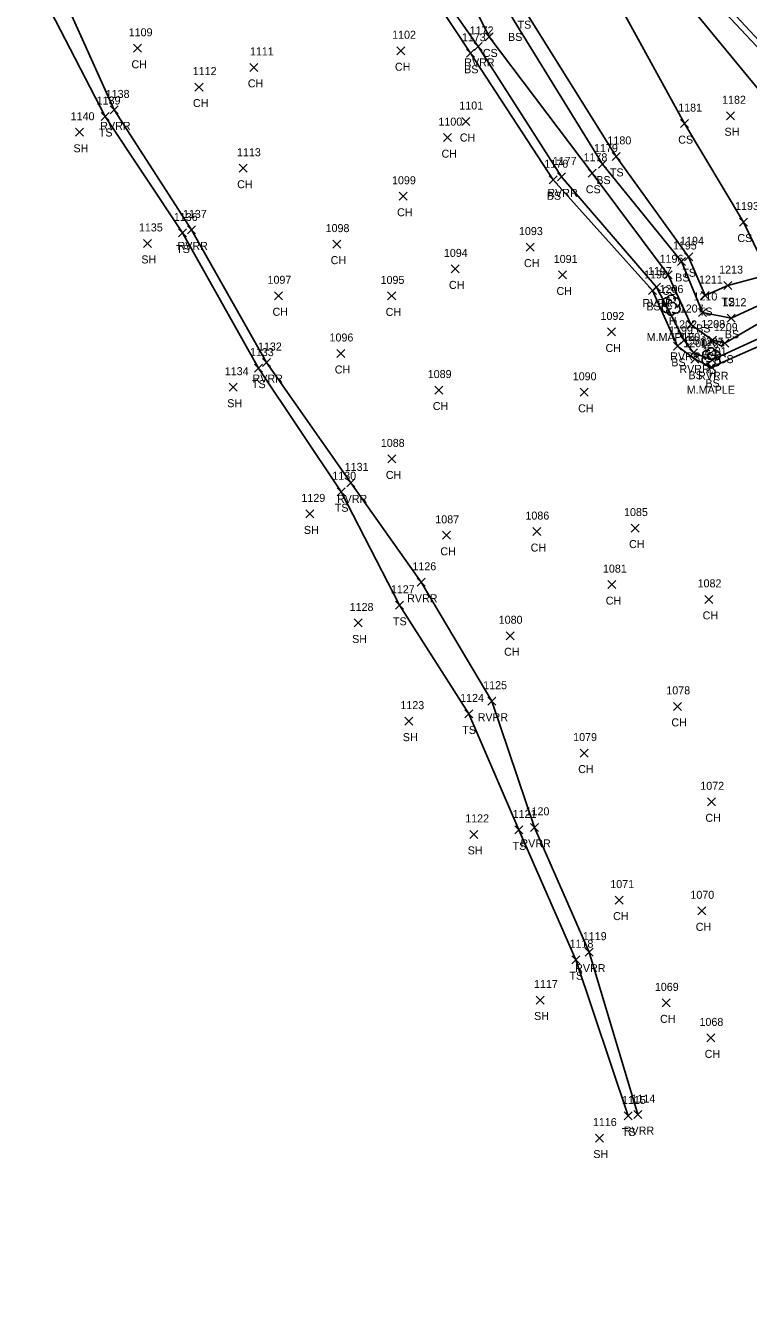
# Model space of a CAD drawing. Extents: x 1469310 to 1475157, y 493997 to 498873.
# Drawn here: x 1469317.8 to 1469498.4, y 498333.7 to 498651.4 of the extents above; entities that cross this region are included whole.
import ezdxf

# ---------------------------------------------------------------- set-up
doc = ezdxf.new("R2010")
doc.units = 0
for name, color, linetype in [('L_A', 7, 'Continuous'), ('L_C', 7, 'Continuous'), ('L_I', 7, 'Continuous'), ('L_TIC', 7, 'Continuous'), ('LAWE', 7, 'Continuous'), ('LELB', 7, 'Continuous'), ('LTD', 7, 'Continuous'), ('PEU', 7, 'Continuous')]:
    doc.layers.add(name, color=color, linetype=linetype)

msp = doc.modelspace()

# ---------------------------------------------------------------- linework, layer by layer
at = {"layer": 'L_TIC'}
for points in [[(1469432.57, 498647.51), (1469434.57, 498649.51)], [(1469434.57, 498647.51), (1469432.57, 498649.51)], [(1469344.77, 498644.67), (1469346.77, 498646.67)], [(1469346.77, 498644.67), (1469344.77, 498646.67)], [(1469410.56, 498644.06), (1469412.56, 498646.06)], [(1469412.56, 498644.06), (1469410.56, 498646.06)], [(1469427.9, 498643.42), (1469429.9, 498645.42)], [(1469429.9, 498643.42), (1469427.9, 498645.42)], [(1469429.85, 498645.13), (1469431.85, 498647.13)], [(1469431.85, 498645.13), (1469429.85, 498647.13)], [(1469373.84, 498639.9), (1469375.84, 498641.9)], [(1469375.84, 498639.9), (1469373.84, 498641.9)], [(1469360.12, 498634.98), (1469362.12, 498636.98)], [(1469362.12, 498634.98), (1469360.12, 498636.98)], [(1469336.69, 498627.62), (1469338.69, 498629.62)], [(1469338.69, 498627.62), (1469336.69, 498629.62)], [(1469338.95, 498629.27), (1469340.95, 498631.27)], [(1469340.95, 498629.27), (1469338.95, 498631.27)], [(1469426.78, 498626.37), (1469428.78, 498628.37)], [(1469428.78, 498626.37), (1469426.78, 498628.37)], [(1469492.89, 498627.81), (1469494.89, 498629.81)], [(1469494.89, 498627.81), (1469492.89, 498629.81)], [(1469330.28, 498623.68), (1469332.28, 498625.68)], [(1469332.28, 498623.68), (1469330.28, 498625.68)], [(1469481.37, 498625.84), (1469483.37, 498627.84)], [(1469483.37, 498625.84), (1469481.37, 498627.84)], [(1469422.21, 498622.34), (1469424.21, 498624.34)], [(1469424.21, 498622.34), (1469422.21, 498624.34)], [(1469464.35, 498617.65), (1469466.35, 498619.65)], [(1469466.35, 498617.65), (1469464.35, 498619.65)], [(1469371.16, 498614.69), (1469373.16, 498616.69)], [(1469373.16, 498614.69), (1469371.16, 498616.69)], [(1469460.92, 498615.73), (1469462.92, 498617.73)], [(1469462.92, 498615.73), (1469460.92, 498617.73)], [(1469448.54, 498611.82), (1469450.54, 498613.82)], [(1469450.54, 498611.82), (1469448.54, 498613.82)], [(1469450.62, 498612.53), (1469452.62, 498614.53)], [(1469452.62, 498612.53), (1469450.62, 498614.53)], [(1469458.29, 498613.44), (1469460.29, 498615.44)], [(1469460.29, 498613.44), (1469458.29, 498615.44)], [(1469411.11, 498607.69), (1469413.11, 498609.69)], [(1469413.11, 498607.69), (1469411.11, 498609.69)], [(1469496.15, 498601.25), (1469498.15, 498603.25)], [(1469498.15, 498601.25), (1469496.15, 498603.25)], [(1469356.01, 498598.52), (1469358.01, 498600.52)], [(1469358.01, 498598.52), (1469356.01, 498600.52)], [(1469358.23, 498599.28), (1469360.23, 498601.28)], [(1469360.23, 498599.28), (1469358.23, 498601.28)], [(1469347.23, 498595.9), (1469349.23, 498597.9)], [(1469349.23, 498595.9), (1469347.23, 498597.9)], [(1469394.52, 498595.73), (1469396.52, 498597.73)], [(1469396.52, 498595.73), (1469394.52, 498597.73)], [(1469442.8, 498594.99), (1469444.8, 498596.99)], [(1469444.8, 498594.99), (1469442.8, 498596.99)], [(1469480.61, 498591.39), (1469482.61, 498593.39)], [(1469482.61, 498591.39), (1469480.61, 498593.39)], [(1469482.42, 498592.57), (1469484.42, 498594.57)], [(1469484.42, 498592.57), (1469482.42, 498594.57)], [(1469424.06, 498589.54), (1469426.06, 498591.54)], [(1469426.06, 498589.54), (1469424.06, 498591.54)], [(1469450.92, 498588.02), (1469452.92, 498590.02)], [(1469452.92, 498588.02), (1469450.92, 498590.02)], [(1469474.38, 498585.01), (1469476.38, 498587.01)], [(1469476.38, 498585.01), (1469474.38, 498587.01)], [(1469477.33, 498588.06), (1469479.33, 498590.06)], [(1469479.33, 498588.06), (1469477.33, 498590.06)], [(1469492.17, 498585.36), (1469494.17, 498587.36)], [(1469494.17, 498585.36), (1469492.17, 498587.36)], [(1469380, 498582.82), (1469382, 498584.82)], [(1469382, 498582.82), (1469380, 498584.82)], [(1469408.24, 498582.79), (1469410.24, 498584.79)], [(1469410.24, 498582.79), (1469408.24, 498584.79)], [(1469473.41, 498584.16), (1469475.41, 498586.16)], [(1469475.41, 498584.16), (1469473.41, 498586.16)], [(1469486.55, 498582.88), (1469488.55, 498584.88)], [(1469488.55, 498582.88), (1469486.55, 498584.88)], [(1469485.84, 498578.65), (1469487.84, 498580.65)], [(1469487.84, 498578.65), (1469485.84, 498580.65)], [(1469482.97, 498575.63), (1469484.97, 498577.63)], [(1469484.97, 498575.63), (1469482.97, 498577.63)], [(1469493.02, 498577.22), (1469495.02, 498579.22)], [(1469495.02, 498577.22), (1469493.02, 498579.22)], [(1469463.17, 498573.78), (1469465.17, 498575.78)], [(1469465.17, 498573.78), (1469463.17, 498575.78)], [(1469479.64, 498570.19), (1469481.64, 498572.19)], [(1469481.64, 498570.19), (1469479.64, 498572.19)], [(1469481.32, 498571.69), (1469483.32, 498573.69)], [(1469483.32, 498571.69), (1469481.32, 498573.69)], [(1469488.34, 498571.76), (1469490.34, 498573.76)], [(1469490.34, 498571.76), (1469488.34, 498573.76)], [(1469491.49, 498570.98), (1469493.49, 498572.98)], [(1469493.49, 498570.98), (1469491.49, 498572.98)], [(1469376.97, 498566.13), (1469378.97, 498568.13)], [(1469378.97, 498566.13), (1469376.97, 498568.13)], [(1469395.54, 498568.4), (1469397.54, 498570.4)], [(1469397.54, 498568.4), (1469395.54, 498570.4)], [(1469483.59, 498568.54), (1469485.59, 498570.54)], [(1469485.59, 498568.54), (1469483.59, 498570.54)], [(1469483.92, 498566.97), (1469485.92, 498568.97)], [(1469485.92, 498566.97), (1469483.92, 498568.97)], [(1469488.26, 498566.84), (1469490.26, 498568.84)], [(1469490.26, 498566.84), (1469488.26, 498568.84)], [(1469374.95, 498564.74), (1469376.95, 498566.74)], [(1469376.95, 498564.74), (1469374.95, 498566.74)], [(1469488.16, 498564.96), (1469490.16, 498566.96)], [(1469490.16, 498564.96), (1469488.16, 498566.96)], [(1469368.69, 498559.97), (1469370.69, 498561.97)], [(1469370.69, 498559.97), (1469368.69, 498561.97)], [(1469420.03, 498559.26), (1469422.03, 498561.26)], [(1469422.03, 498559.26), (1469420.03, 498561.26)], [(1469456.33, 498558.7), (1469458.33, 498560.7)], [(1469458.33, 498558.7), (1469456.33, 498560.7)], [(1469408.3, 498542.05), (1469410.3, 498544.05)], [(1469410.3, 498542.05), (1469408.3, 498544.05)], [(1469398.07, 498536.07), (1469400.07, 498538.07)], [(1469400.07, 498536.07), (1469398.07, 498538.07)], [(1469395.62, 498533.84), (1469397.62, 498535.84)], [(1469397.62, 498533.84), (1469395.62, 498535.84)], [(1469387.83, 498528.31), (1469389.83, 498530.31)], [(1469389.83, 498528.31), (1469387.83, 498530.31)], [(1469469.05, 498524.77), (1469471.05, 498526.77)], [(1469471.05, 498524.77), (1469469.05, 498526.77)], [(1469421.91, 498522.96), (1469423.91, 498524.96)], [(1469423.91, 498522.96), (1469421.91, 498524.96)], [(1469444.47, 498523.89), (1469446.47, 498525.89)], [(1469446.47, 498523.89), (1469444.47, 498525.89)], [(1469415.6, 498511.22), (1469417.6, 498513.22)], [(1469417.6, 498511.22), (1469415.6, 498513.22)], [(1469463.22, 498510.64), (1469465.22, 498512.64)], [(1469465.22, 498510.64), (1469463.22, 498512.64)], [(1469487.42, 498506.95), (1469489.42, 498508.95)], [(1469489.42, 498506.95), (1469487.42, 498508.95)], [(1469410.17, 498505.47), (1469412.17, 498507.47)], [(1469412.17, 498505.47), (1469410.17, 498507.47)], [(1469399.88, 498501.05), (1469401.88, 498503.05)], [(1469401.88, 498501.05), (1469399.88, 498503.05)], [(1469437.84, 498497.86), (1469439.84, 498499.86)], [(1469439.84, 498497.86), (1469437.84, 498499.86)], [(1469433.22, 498481.51), (1469435.22, 498483.51)], [(1469435.22, 498481.51), (1469433.22, 498483.51)], [(1469479.61, 498480.21), (1469481.61, 498482.21)], [(1469481.61, 498480.21), (1469479.61, 498482.21)], [(1469427.48, 498478.32), (1469429.48, 498480.32)], [(1469429.48, 498478.32), (1469427.48, 498480.32)], [(1469412.54, 498476.52), (1469414.54, 498478.52)], [(1469414.54, 498476.52), (1469412.54, 498478.52)], [(1469456.35, 498468.54), (1469458.35, 498470.54)], [(1469458.35, 498468.54), (1469456.35, 498470.54)], [(1469488.1, 498456.36), (1469490.1, 498458.36)], [(1469490.1, 498456.36), (1469488.1, 498458.36)], [(1469440.03, 498449.34), (1469442.03, 498451.34)], [(1469442.03, 498449.34), (1469440.03, 498451.34)], [(1469443.89, 498449.98), (1469445.89, 498451.98)], [(1469445.89, 498449.98), (1469443.89, 498451.98)], [(1469428.73, 498448.22), (1469430.73, 498450.22)], [(1469430.73, 498448.22), (1469428.73, 498450.22)], [(1469465.06, 498431.8), (1469467.06, 498433.8)], [(1469467.06, 498431.8), (1469465.06, 498433.8)], [(1469485.7, 498429.12), (1469487.7, 498431.12)], [(1469487.7, 498429.12), (1469485.7, 498431.12)], [(1469454.23, 498416.9), (1469456.23, 498418.9)], [(1469456.23, 498416.9), (1469454.23, 498418.9)], [(1469457.55, 498418.79), (1469459.55, 498420.79)], [(1469459.55, 498418.79), (1469457.55, 498420.79)], [(1469445.34, 498406.83), (1469447.34, 498408.83)], [(1469447.34, 498406.83), (1469445.34, 498408.83)], [(1469476.8, 498406.12), (1469478.8, 498408.12)], [(1469478.8, 498406.12), (1469476.8, 498408.12)], [(1469487.94, 498397.36), (1469489.94, 498399.36)], [(1469489.94, 498397.36), (1469487.94, 498399.36)], [(1469467.33, 498377.85), (1469469.33, 498379.85)], [(1469469.33, 498377.85), (1469467.33, 498379.85)], [(1469469.69, 498378.21), (1469471.69, 498380.21)], [(1469471.69, 498378.21), (1469469.69, 498380.21)], [(1469460.11, 498372.33), (1469462.11, 498374.33)], [(1469462.11, 498372.33), (1469460.11, 498374.33)]]:
    msp.add_lwpolyline(points, dxfattribs=at)
at = {"layer": 'LAWE'}
for points in [[(1469389.72, 498705.76), (1469405.14, 498682.89), (1469430.85, 498646.13), (1469451.62, 498613.53), (1469475.38, 498586.01), (1469482.32, 498572.69), (1469484.59, 498569.54), (1469489.26, 498567.84), (1469509.66, 498577.17), (1469522.84, 498580.18), (1469533.51, 498579.28), (1469530.31, 498572.64)], [(1469470.69, 498379.21), (1469458.55, 498419.79), (1469444.89, 498450.98), (1469434.22, 498482.51), (1469416.6, 498512.22), (1469399.07, 498537.07), (1469377.97, 498567.13), (1469359.23, 498600.28), (1469339.95, 498630.27), (1469322.53, 498669.03)]]:
    msp.add_lwpolyline(points, dxfattribs=at)
at = {"layer": 'LELB'}
for points in [[(1469416.82, 498734.31), (1469446.33, 498703.1), (1469470.89, 498677.65), (1469509.28, 498636.71), (1469524.42, 498615.8), (1469544.37, 498592.02), (1469564.88, 498563.16), (1469574.6, 498542.86), (1469576.57, 498532.67), (1469562.98, 498525.95), (1469548.2, 498517.37), (1469540.61, 498511.22), (1469554.07, 498484.99), (1469566.51, 498459.59)], [(1469413.42, 498730.94), (1469442.52, 498698.7), (1469468.45, 498674.77), (1469500.53, 498635.82), (1469519, 498614.53), (1469533.17, 498594.86), (1469544.52, 498587.12), (1469562.89, 498554.7), (1469567.79, 498543.52), (1469559.26, 498528.6), (1469545.4, 498521.66), (1469536.79, 498513.03)], [(1469407.36, 498725.91), (1469434.35, 498693.87), (1469460.14, 498667.42), (1469482.37, 498626.84), (1469497.15, 498602.25), (1469503.47, 498589.17)], [(1469403.96, 498707.9), (1469421.49, 498683.84), (1469442.27, 498655.57), (1469465.35, 498618.65), (1469483.42, 498593.57), (1469487.55, 498583.88), (1469493.17, 498586.36), (1469503.47, 498589.17), (1469519.52, 498592.82), (1469533.17, 498594.86)], [(1469387.88, 498704.33), (1469404.11, 498681.98), (1469428.9, 498644.42), (1469449.54, 498612.82), (1469474.41, 498585.16), (1469480.64, 498571.19), (1469484.92, 498567.97), (1469489.16, 498565.96), (1469510.3, 498575.29), (1469522.97, 498578.34), (1469531.66, 498578.29)], [(1469468.33, 498378.85), (1469455.23, 498417.9), (1469441.03, 498450.34), (1469428.48, 498479.32), (1469411.17, 498506.47), (1469396.62, 498534.84), (1469375.95, 498565.74), (1469357.01, 498599.52), (1469337.69, 498628.62), (1469317.77, 498667.17)], [(1469434.43, 498661.86), (1469439.87, 498652.51), (1469461.92, 498616.73), (1469481.61, 498592.39), (1469486.84, 498579.65), (1469494.02, 498578.22), (1469506.13, 498583.82), (1469519.69, 498588.79), (1469534.49, 498586.2), (1469541.72, 498579.08), (1469557.44, 498552.67)], [(1469428.53, 498658.9), (1469433.57, 498648.51), (1469459.29, 498614.44), (1469478.33, 498589.06), (1469483.97, 498576.63), (1469489.34, 498572.76), (1469492.49, 498571.98), (1469507.99, 498581.09), (1469520.42, 498585.29), (1469534.63, 498584.29), (1469538.32, 498574.02), (1469547.83, 498560.42), (1469557.44, 498552.67), (1469555.67, 498535.67), (1469539.85, 498524.73), (1469536.79, 498513.03), (1469549.04, 498482.48), (1469564.46, 498458.05), (1469576.5, 498438.75), (1469578.88, 498431.59)]]:
    msp.add_lwpolyline(points, dxfattribs=at)
at = {"layer": 'LTD'}
for p, q in [((1469478.99, 498581.51), (1469478.99, 498581.51)), ((1469478.99, 498581.51), (1469478.99, 498581.51)), ((1469489, 498568.34), (1469489, 498568.34)), ((1469489, 498568.34), (1469489, 498568.34))]:
    msp.add_line(p, q, dxfattribs=at)
for centre in [(1469479.03, 498582.94), (1469489.05, 498569.77)]:
    msp.add_arc(centre, 1.05, 335.5272, 180.9563, dxfattribs=at)
for centre, major_axis, ratio, start_param, end_param in [((1469477.9, 498580.8), (0.58, -1.04), 0.959034, 3.141593, 6.283185), ((1469478.19, 498582.17), (1.21, -0.51), 0.895232, 1.570796, 4.712389), ((1469478.53, 498580.76), (-0.625, -0.083), 0.423636, 0, 3.141593), ((1469478.78, 498581.96), (-0.208, -0.792), 0.645439, 3.141593, 6.283185), ((1469479.49, 498581.34), (-0.5, 0.667), 0.989748, 3.141593, 6.283185), ((1469479.99, 498580.67), (-1.09, 0.79), 0.841452, 1.570796, 4.712389), ((1469480.03, 498582.09), (-1.14, -0.48), 0.949671, 1.570796, 4.712389), ((1469478.99, 498580.01), (0.26, 1.06), 0.942809, 1.570796, 4.712389), ((1469487.92, 498567.63), (0.58, -1.04), 0.959034, 3.141593, 6.283185), ((1469488.21, 498569), (1.21, -0.51), 0.895232, 1.570796, 4.712389), ((1469488.79, 498568.79), (-0.208, -0.792), 0.645439, 3.141593, 6.283185), ((1469489.5, 498568.17), (-0.5, 0.667), 0.989748, 3.141593, 6.283185), ((1469490, 498567.5), (-1.09, 0.79), 0.841452, 1.570796, 4.712389), ((1469490.04, 498568.92), (-1.14, -0.48), 0.949671, 1.570796, 4.712389), ((1469489, 498566.84), (0.26, 1.06), 0.942809, 1.570796, 4.712389), ((1469488.54, 498567.59), (-0.625, -0.083), 0.423636, 0, 3.141593)]:
    msp.add_ellipse(centre, major_axis=major_axis, ratio=ratio, start_param=start_param, end_param=end_param, dxfattribs=at)
at = {"layer": 'PEU'}
msp.add_lwpolyline([(1469418.16, 498735.54), (1469447.91, 498704.22), (1469471.83, 498679.03), (1469509.9, 498637.99), (1469529.4, 498614.8), (1469545.14, 498594.13), (1469565.65, 498563.08), (1469576.41, 498543.24), (1469581.13, 498534.68), (1469591.75, 498510.08), (1469602.71, 498485.38), (1469609.03, 498458.44), (1469615.47, 498438.56), (1469621.98, 498404.81), (1469621.72, 498400.42), (1469625.38, 498362.57), (1469626.2, 498333.72)], dxfattribs=at)

# ---------------------------------------------------------------- texts
at = {"layer": 'L_A'}
for s, p in [('TS', (1469440.68, 498650.57)), ('BS', (1469438.31, 498647.51)), ('CS', (1469432.01, 498643.51)), ('CH', (1469344.26, 498640.67)), ('CH', (1469410.05, 498640.06)), ('BS', (1469427.34, 498639.42)), ('RVRR', (1469427.37, 498641.13)), ('CH', (1469373.32, 498635.9)), ('CH', (1469359.61, 498630.98)), ('TS', (1469336.1, 498623.62)), ('RVRR', (1469336.46, 498625.27)), ('SH', (1469492.38, 498623.81)), ('CH', (1469426.27, 498622.37)), ('CS', (1469480.81, 498621.84)), ('SH', (1469329.77, 498619.68)), ('CH', (1469421.7, 498618.34)), ('TS', (1469463.76, 498613.65)), ('CH', (1469370.65, 498610.69)), ('BS', (1469460.36, 498611.73)), ('BS', (1469447.98, 498607.82)), ('RVRR', (1469448.13, 498608.53)), ('CS', (1469457.73, 498609.44)), ('CH', (1469410.6, 498603.69)), ('TS', (1469355.42, 498594.52)), ('RVRR', (1469355.74, 498595.28)), ('CS', (1469495.59, 498597.25)), ('SH', (1469346.72, 498591.9)), ('CH', (1469394, 498591.73)), ('CH', (1469442.29, 498590.99)), ('TS', (1469481.83, 498588.57)), ('CH', (1469423.54, 498585.54)), ('BS', (1469480.05, 498587.39)), ('CH', (1469450.41, 498584.02)), ('CS', (1469476.77, 498584.06)), ('CH', (1469379.49, 498578.82)), ('CH', (1469407.73, 498578.79)), ('RVRR', (1469471.89, 498581.01)), ('BS', (1469472.85, 498580.16)), ('TS', (1469485.96, 498578.88)), ('TS', (1469491.58, 498581.36)), ('H', (1469478.42, 498576.51)), ('BS', (1469485.28, 498574.65)), ('BS', (1469492.46, 498573.22)), ('CH', (1469462.66, 498569.78)), ('CS', (1469482.41, 498571.63)), ('RVRR', (1469478.83, 498567.69)), ('BS', (1469479.08, 498566.19)), ('CS', (1469487.78, 498567.76)), ('CS', (1469490.93, 498566.98)), ('CH', (1469395.03, 498564.4)), ('RVRR', (1469481.1, 498564.54)), ('BS', (1469483.37, 498562.97)), ('RVRR', (1469485.78, 498562.84)), ('H', (1469488.43, 498563.34)), ('TS', (1469374.36, 498560.74)), ('RVRR', (1469374.48, 498562.13)), ('BS', (1469487.6, 498560.96)), ('SH', (1469368.17, 498555.97)), ('CH', (1469419.52, 498555.26)), ('CH', (1469455.81, 498554.7)), ('CH', (1469407.79, 498538.05)), ('RVRR', (1469395.58, 498532.07)), ('TS', (1469395.03, 498529.84)), ('SH', (1469387.32, 498524.31)), ('CH', (1469421.4, 498518.96)), ('CH', (1469443.96, 498519.89)), ('CH', (1469468.54, 498520.77)), ('RVRR', (1469413.11, 498507.22)), ('CH', (1469462.71, 498506.64)), ('CH', (1469486.91, 498502.95)), ('TS', (1469409.58, 498501.47)), ('SH', (1469399.37, 498497.05)), ('CH', (1469437.32, 498493.86)), ('RVRR', (1469430.73, 498477.51)), ('TS', (1469426.89, 498474.32)), ('CH', (1469479.1, 498476.21)), ('SH', (1469412.03, 498472.52)), ('CH', (1469455.83, 498464.54)), ('CH', (1469487.59, 498452.36)), ('TS', (1469439.44, 498445.34)), ('RVRR', (1469441.4, 498445.98)), ('SH', (1469428.22, 498444.22)), ('CH', (1469464.55, 498427.8)), ('CH', (1469485.19, 498425.12)), ('RVRR', (1469455.07, 498414.79)), ('TS', (1469453.64, 498412.9)), ('SH', (1469444.83, 498402.83)), ('CH', (1469476.29, 498402.12)), ('CH', (1469487.43, 498393.36)), ('TS', (1469466.74, 498373.85)), ('RVRR', (1469467.21, 498374.21)), ('SH', (1469459.6, 498368.33))]:
    msp.add_text(s, height=2, dxfattribs=at).set_placement(p)
at = {"layer": 'L_C'}
for p in [(1469472.92, 498572.51), (1469482.94, 498559.34)]:
    msp.add_text('M.MAPLE', height=2, dxfattribs=at).set_placement(p)
at = {"layer": 'L_I'}
for s, p in [('1109', (1469343.56, 498648.67)), ('1172', (1469428.73, 498649.13)), ('1102', (1469409.36, 498648.06)), ('1173', (1469426.78, 498647.42)), ('1111', (1469373.84, 498643.9)), ('1112', (1469359.56, 498638.98)), ('1138', (1469337.82, 498633.27)), ('1139', (1469335.56, 498631.62)), ('1101', (1469426.14, 498630.37)), ('1181', (1469480.81, 498629.84)), ('1182', (1469491.77, 498631.81)), ('1140', (1469329.07, 498627.68)), ('1100', (1469420.92, 498626.34)), ('1180', (1469463.14, 498621.65)), ('1113', (1469370.6, 498618.69)), ('1178', (1469457.16, 498617.44)), ('1179', (1469459.78, 498619.73)), ('1176', (1469447.36, 498615.82)), ('1177', (1469449.49, 498616.53)), ('1099', (1469409.33, 498611.69)), ('1193', (1469495.02, 498605.25)), ('1136', (1469354.83, 498602.52)), ('1137', (1469357.1, 498603.28)), ('1135', (1469346.11, 498599.9)), ('1098', (1469392.74, 498599.73)), ('1093', (1469441.03, 498598.99)), ('1195', (1469479.48, 498595.39)), ('1194', (1469481.29, 498596.57)), ('1094', (1469422.28, 498593.54)), ('1091', (1469449.72, 498592.02)), ('1196', (1469476.15, 498592.06)), ('1198', (1469472.29, 498588.16)), ('1197', (1469473.25, 498589.01)), ('1213', (1469491.04, 498589.36)), ('1097', (1469378.23, 498586.82)), ('1095', (1469406.47, 498586.79)), ('1211', (1469486, 498586.88)), ('1206', (1469476.16, 498584.51)), ('1210', (1469484.62, 498582.65)), ('1207', (1469481.2, 498579.63)), ('1212', (1469491.9, 498581.22)), ('1092', (1469461.4, 498577.78)), ('1202', (1469479.55, 498575.69)), ('1208', (1469486.57, 498575.76)), ('1096', (1469393.72, 498572.4)), ('1199', (1469478.51, 498574.19)), ('1203', (1469481.82, 498572.54)), ('1209', (1469489.71, 498574.98)), ('1132', (1469375.84, 498570.13)), ('1200', (1469482.07, 498570.97)), ('1205', (1469486.23, 498571.34)), ('1204', (1469486.49, 498570.84)), ('1133', (1469373.83, 498568.74)), ('1201', (1469486.95, 498568.96)), ('1134', (1469367.56, 498563.97)), ('1089', (1469418.25, 498563.26)), ('1090', (1469454.47, 498562.7)), ('1088', (1469406.53, 498546.05)), ('1130', (1469394.41, 498537.84)), ('1131', (1469397.51, 498540.07)), ('1129', (1469386.7, 498532.31)), ('1086', (1469442.65, 498527.89)), ('1085', (1469467.28, 498528.77)), ('1087', (1469420.14, 498526.96)), ('1126', (1469414.42, 498515.22)), ('1081', (1469462.01, 498514.64)), ('1127', (1469409.04, 498509.47)), ('1082', (1469485.65, 498510.95)), ('1128', (1469398.75, 498505.05)), ('1080', (1469435.98, 498501.86)), ('1125', (1469432.1, 498485.51)), ('1078', (1469477.84, 498484.21)), ('1123', (1469411.42, 498480.52)), ('1124', (1469426.35, 498482.32)), ('1079', (1469454.57, 498472.54)), ('1072', (1469486.33, 498460.36)), ('1122', (1469427.61, 498452.22)), ('1121', (1469439.47, 498453.34)), ('1120', (1469442.68, 498453.98)), ('1071', (1469463.85, 498435.8)), ('1070', (1469483.85, 498433.12)), ('1118', (1469453.67, 498420.9)), ('1119', (1469456.99, 498422.79)), ('1117', (1469444.79, 498410.83)), ('1069', (1469474.98, 498410.12)), ('1068', (1469486.12, 498401.36)), ('1115', (1469466.77, 498381.85)), ('1114', (1469469.14, 498382.21)), ('1116', (1469459.5, 498376.33))]:
    msp.add_text(s, height=2, dxfattribs=at).set_placement(p)

doc.saveas('drawing.dxf')
